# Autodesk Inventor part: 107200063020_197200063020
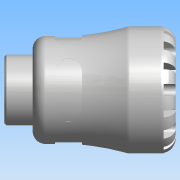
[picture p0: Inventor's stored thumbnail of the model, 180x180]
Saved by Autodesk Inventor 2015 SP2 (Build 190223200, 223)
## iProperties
Created: 2016-12
Part Number: 107200063020_197200063020
Material: PVC-Piping
Description: PLASSON MALE INTEGRAL BRASS THREAD 63X2" SERIES 1
Document SubType Name: Modeling
Designer: KIM
Mass: 61.7504 g
Surface Area: 140.097 cm^2
Volume: 44.1074 cm^3
Density: 1.4 g/cm^3
Appearance: Smooth - White
Author: KIM
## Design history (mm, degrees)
derived "1072.ipt"
feature "Solid1::1072.ipt"
tag "TaggingFeature1"
body "Solid1"
other parameters: "d0" = 139, "d1" = 38.64, "d2" = 63, "d3" = 78.75, "d4" = 103, "d6" = 92, "d8" = 87.55, "d13" = 9.7, "d14" = 9.7, "d15" = 0, "d17" = 360 deg, "d19" = 8 deg, "d20" = 1.26, "d21" = 1.26, "d22" = 8 deg, "d24" = 0, "d26" = 360 deg, "d32" = 10.3, "d33" = 10.3, "d34" = 57.296, "d38" = 23, "d39" = 1.71888, "d42" = 22.05, "d43" = 14.49, "d45" = 19.012, "d46" = 0, "d59" = 360 deg, "d61" = 18.7425, "d62" = 1.26, "d64" = 0, "d65" = 1.03, "d68" = 9, "d_" = 63, "E_" = 103, "H_" = 139, "l_" = 92, "R_" = 57.296, "l_2" = 23, "d9" = 12.125, "d11" = 103, "d12" = 78.75
